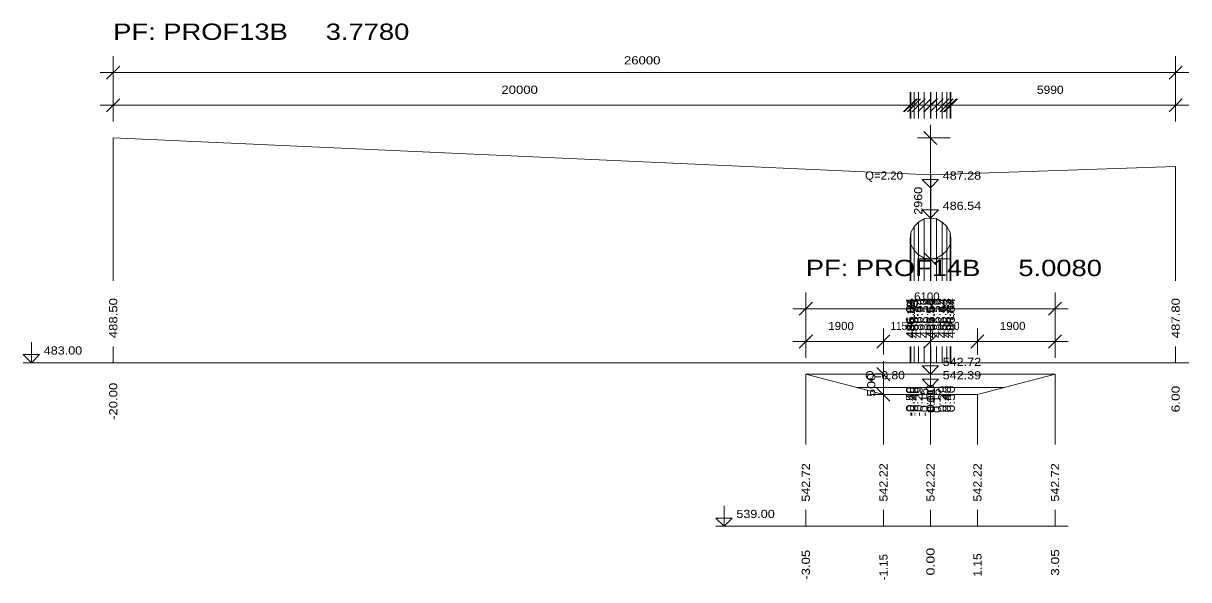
# Model space of a CAD drawing. Extents: x 7 to 442, y -393 to 441.
# Drawn here: x 399.84 to 428.36, y -294.34 to -280.73 of the extents above; entities that cross this region are included whole.
import ezdxf

# ---------------------------------------------------------------- set-up
doc = ezdxf.new("R2010")
doc.units = 0
doc.header["$LTSCALE"] = 0.08
doc.layers.add('7', color=7, linetype='Continuous', lineweight=13)

msp = doc.modelspace()

# ---------------------------------------------------------------- linework, layer by layer
at = {"layer": '7'}
for p, q in [((401.878, -282.094), (402.198, -281.774)), ((402.038, -283.134), (402.038, -281.534)), ((427.878, -282.094), (428.198, -281.774)), ((428.038, -283.134), (428.038, -281.534)), ((401.718, -281.934), (428.358, -281.934)), ((401.878, -282.894), (402.198, -282.574)), ((402.038, -283.054), (402.038, -282.414)), ((421.378, -282.894), (421.698, -282.574)), ((421.398, -282.894), (421.718, -282.574)), ((421.398, -282.894), (421.718, -282.574)), ((421.478, -282.894), (421.798, -282.574)), ((421.478, -282.894), (421.798, -282.574)), ((421.538, -283.054), (421.538, -282.414)), ((421.558, -283.054), (421.558, -282.414)), ((421.558, -283.054), (421.558, -282.414)), ((421.588, -282.894), (421.908, -282.574)), ((421.588, -282.894), (421.908, -282.574)), ((421.638, -283.054), (421.638, -282.414)), ((421.638, -283.054), (421.638, -282.414)), ((421.728, -282.894), (422.048, -282.574)), ((421.728, -282.894), (422.048, -282.574)), ((421.748, -283.054), (421.748, -282.414)), ((421.748, -283.054), (421.748, -282.414)), ((421.878, -282.894), (422.198, -282.574)), ((421.878, -282.894), (422.198, -282.574)), ((421.878, -282.894), (422.198, -282.574)), ((421.888, -283.054), (421.888, -282.414)), ((421.888, -283.054), (421.888, -282.414)), ((421.888, -282.894), (422.208, -282.574)), ((421.888, -282.894), (422.208, -282.574)), ((422.028, -282.894), (422.348, -282.574)), ((422.028, -282.894), (422.348, -282.574)), ((422.038, -283.054), (422.038, -282.414)), ((422.038, -283.054), (422.038, -282.414)), ((422.038, -283.054), (422.038, -282.414)), ((422.048, -283.054), (422.048, -282.414)), ((422.048, -283.054), (422.048, -282.414)), ((422.168, -282.894), (422.488, -282.574)), ((422.168, -282.894), (422.488, -282.574)), ((422.188, -283.054), (422.188, -282.414)), ((422.188, -283.054), (422.188, -282.414)), ((422.278, -282.894), (422.598, -282.574)), ((422.278, -282.894), (422.598, -282.574)), ((422.328, -283.054), (422.328, -282.414)), ((422.328, -283.054), (422.328, -282.414)), ((422.358, -282.894), (422.678, -282.574)), ((422.358, -282.894), (422.678, -282.574)), ((422.378, -282.894), (422.698, -282.574)), ((422.438, -283.054), (422.438, -282.414)), ((422.438, -283.054), (422.438, -282.414)), ((422.518, -283.054), (422.518, -282.414)), ((422.518, -283.054), (422.518, -282.414)), ((422.538, -283.054), (422.538, -282.414)), ((427.878, -282.894), (428.198, -282.574)), ((428.038, -283.054), (428.038, -282.414)), ((401.718, -282.734), (428.358, -282.734)), ((422.198, -283.694), (421.878, -283.374)), ((422.038, -286.654), (422.038, -283.214)), ((402.038, -287.034), (402.038, -283.534)), ((421.718, -283.534), (422.518, -283.534)), ((428.038, -287.034), (428.038, -284.234)), ((422.038, -287.034), (422.038, -284.434)), ((422.048, -287.034), (422.048, -284.434)), ((422.038, -284.754), (422.048, -284.754)), ((421.638, -287.034), (421.638, -285.704)), ((421.748, -287.034), (421.748, -285.594)), ((421.888, -287.034), (421.888, -285.514)), ((422.038, -287.034), (422.038, -285.494)), ((422.038, -285.494), (422.048, -285.494)), ((422.048, -287.034), (422.048, -285.494)), ((422.188, -287.034), (422.188, -285.514)), ((422.328, -287.034), (422.328, -285.594)), ((422.438, -287.034), (422.438, -285.704)), ((421.538, -287.034), (421.538, -285.994)), ((421.558, -287.034), (421.558, -285.844)), ((422.518, -287.034), (422.518, -285.844)), ((422.538, -287.034), (422.538, -285.994)), ((421.558, -287.034), (421.558, -286.144)), ((421.638, -287.034), (421.638, -286.284)), ((422.198, -286.654), (421.878, -286.334)), ((422.438, -287.034), (422.438, -286.284)), ((422.518, -287.034), (422.518, -286.144)), ((421.718, -286.494), (422.518, -286.494)), ((421.748, -287.034), (421.748, -286.394)), ((421.888, -287.034), (421.888, -286.474)), ((422.038, -287.034), (422.038, -286.494)), ((422.188, -287.034), (422.188, -286.474)), ((422.328, -287.034), (422.328, -286.394)), ((418.988, -288.914), (418.988, -287.314)), ((425.088, -288.914), (425.088, -287.314)), ((418.668, -287.714), (425.408, -287.714)), ((418.828, -287.874), (419.148, -287.554)), ((424.928, -287.874), (425.248, -287.554)), ((418.988, -288.834), (418.988, -288.194)), ((420.888, -288.834), (420.888, -288.194)), ((422.038, -288.834), (422.038, -288.194)), ((423.188, -288.834), (423.188, -288.194)), ((425.088, -288.834), (425.088, -288.194)), ((418.668, -288.514), (425.408, -288.514)), ((418.828, -288.674), (419.148, -288.354)), ((420.728, -288.674), (421.048, -288.354)), ((421.878, -288.674), (422.198, -288.354)), ((423.028, -288.674), (423.348, -288.354)), ((424.928, -288.674), (425.248, -288.354)), ((402.038, -289.034), (402.038, -288.634)), ((421.538, -289.034), (421.538, -288.634)), ((421.558, -289.034), (421.558, -288.634)), ((421.558, -289.034), (421.558, -288.634)), ((421.638, -289.034), (421.638, -288.634)), ((421.638, -289.034), (421.638, -288.634)), ((421.748, -289.034), (421.748, -288.634)), ((421.748, -289.034), (421.748, -288.634)), ((421.888, -289.034), (421.888, -288.634)), ((421.888, -289.034), (421.888, -288.634)), ((422.038, -289.034), (422.038, -288.634)), ((422.038, -289.034), (422.038, -288.634)), ((422.038, -289.034), (422.038, -288.634)), ((422.048, -289.034), (422.048, -288.634)), ((422.048, -289.034), (422.048, -288.634)), ((422.188, -289.034), (422.188, -288.634)), ((422.188, -289.034), (422.188, -288.634)), ((422.328, -289.034), (422.328, -288.634)), ((422.328, -289.034), (422.328, -288.634)), ((422.438, -289.034), (422.438, -288.634)), ((422.438, -289.034), (422.438, -288.634)), ((422.518, -289.034), (422.518, -288.634)), ((422.518, -289.034), (422.518, -288.634)), ((422.538, -289.034), (422.538, -288.634)), ((428.038, -289.034), (428.038, -288.634)), ((399.838, -289.034), (428.358, -289.034)), ((421.048, -289.474), (420.728, -289.154)), ((420.888, -289.974), (420.888, -288.994)), ((418.988, -291.034), (418.988, -289.314)), ((418.988, -289.314), (425.088, -289.314)), ((420.568, -289.314), (421.368, -289.314)), ((425.088, -291.034), (425.088, -289.314)), ((420.227, -289.64), (423.849, -289.64)), ((421.048, -289.974), (420.728, -289.654)), ((420.568, -289.814), (421.368, -289.814)), ((420.888, -291.034), (420.888, -289.814)), ((422.038, -291.034), (422.038, -289.814)), ((423.188, -291.034), (423.188, -289.814)), ((418.988, -293.034), (418.988, -292.634)), ((420.888, -293.034), (420.888, -292.634)), ((422.038, -293.034), (422.038, -292.634)), ((423.188, -293.034), (423.188, -292.634)), ((425.088, -293.034), (425.088, -292.634)), ((416.788, -293.034), (425.408, -293.034))]:
    msp.add_line(p, q, dxfattribs=at)
for points in [[(402.038, -283.534), (422.038, -284.434), (422.038, -285.494), (421.888, -285.514), (421.748, -285.594), (421.638, -285.704), (421.558, -285.844), (421.538, -285.994), (421.558, -286.144), (421.638, -286.284), (421.748, -286.394), (421.888, -286.474), (422.038, -286.494), (422.188, -286.474), (422.328, -286.394), (422.438, -286.284), (422.518, -286.144), (422.538, -285.994), (422.518, -285.844), (422.438, -285.704), (422.328, -285.594), (422.188, -285.514), (422.048, -285.494), (422.048, -284.434), (428.038, -284.234)], [(422.038, -284.254), (422.038, -284.754), (421.838, -284.554), (422.238, -284.554), (422.038, -284.754)], [(422.038, -284.994), (422.038, -285.494), (421.838, -285.294), (422.238, -285.294), (422.038, -285.494)], [(400.038, -288.534), (400.038, -289.034), (399.838, -288.834), (400.238, -288.834), (400.038, -289.034)], [(422.038, -288.814), (422.038, -289.314), (421.838, -289.114), (422.238, -289.114), (422.038, -289.314)], [(422.038, -289.14), (422.038, -289.64), (421.838, -289.44), (422.238, -289.44), (422.038, -289.64)], [(418.988, -289.314), (420.888, -289.814), (422.038, -289.814), (423.188, -289.814), (425.088, -289.314)], [(416.988, -292.534), (416.988, -293.034), (416.788, -292.834), (417.188, -292.834), (416.988, -293.034)]]:
    msp.add_lwpolyline(points, dxfattribs=at)

# ---------------------------------------------------------------- texts
for s, height, width, p in [('PF: PROF13B     3.7780', 0.4, 1.25, (402.038, -281.134)), ('26000', 0.2, 1.2, (414.538, -281.734)), ('20000', 0.2, 1.2, (411.538, -282.454)), ('5990', 0.2, 1.1, (424.643, -282.454)), ('Q=2.20', 0.2, 1.05, (420.438, -284.554)), ('487.28', 0.2, 1.15, (422.338, -284.554)), ('486.54', 0.2, 1.15, (422.338, -285.294)), ('PF: PROF14B     5.0080', 0.4, 1.25, (418.988, -286.914)), ('6100', 0.2, 1.05, (421.638, -287.514)), ('1900', 0.2, 1.05, (419.538, -288.234)), ('1150', 0.2, 0.9, (421.063, -288.234)), ('1150', 0.2, 0.9, (422.213, -288.234)), ('1900', 0.2, 1.05, (423.738, -288.234)), ('483.00', 0.2, 1.15, (400.338, -288.834)), ('542.72', 0.2, 1.15, (422.338, -289.114)), ('Q=0.80', 0.2, 1.1, (420.438, -289.44)), ('542.39', 0.2, 1.15, (422.338, -289.44)), ('539.00', 0.2, 1.15, (417.288, -292.834))]:
    msp.add_text(s, height=height, dxfattribs=dict(at, width=width)).set_placement(p)
for s, width, p in [('2960', 1.15, (421.838, -285.414)), ('488.50 ', 1.2, (402.138, -288.434)), ('486.04 ', 1.2, (421.638, -288.434)), ('486.33 ', 1.2, (421.738, -288.434)), ('486.44 ', 1.2, (421.848, -288.434)), ('485.64 ', 1.2, (421.848, -288.434)), ('485.56 ', 1.2, (421.988, -288.434)), ('486.52 ', 1.2, (421.988, -288.434)), ('486.54 ', 1.2, (422.138, -288.434)), ('487.60 ', 1.2, (422.138, -288.434)), ('486.54 ', 1.2, (422.148, -288.434)), ('487.60 ', 1.2, (422.148, -288.434)), ('485.56 ', 1.2, (422.288, -288.434)), ('486.52 ', 1.2, (422.288, -288.434)), ('485.64 ', 1.2, (422.428, -288.434)), ('486.44 ', 1.2, (422.428, -288.434)), ('486.33 ', 1.2, (422.538, -288.434)), ('486.04 ', 1.2, (422.638, -288.434)), ('487.80 ', 1.2, (428.138, -288.434)), ('485.89 ', 1.15, (421.658, -288.434)), ('486.19 ', 1.1, (421.658, -288.434)), ('485.75 ', 1.15, (421.738, -288.434)), ('485.54 ', 1.15, (422.138, -288.434)), ('485.75 ', 1.15, (422.538, -288.434)), ('485.89 ', 1.15, (422.618, -288.434)), ('486.19 ', 1.1, (422.618, -288.434)), (' 500', 1.3, (420.688, -289.964)), ('-20.00 ', 1.2, (402.138, -290.434)), (' -0.50 ', 1.2, (421.638, -290.434)), (' -0.48 ', 1.2, (421.658, -290.434)), (' -0.48 ', 1.2, (421.658, -290.434)), (' -0.40 ', 1.2, (421.738, -290.434)), (' -0.40 ', 1.2, (421.738, -290.434)), (' -0.29 ', 1.2, (421.848, -290.434)), (' -0.29 ', 1.2, (421.848, -290.434)), (' -0.15 ', 1.15, (421.988, -290.434)), (' -0.15 ', 1.15, (421.988, -290.434)), ('  0.00 ', 1.3, (422.138, -290.434)), ('  0.00 ', 1.3, (422.138, -290.434)), ('  0.00 ', 1.3, (422.138, -290.434)), ('  0.01 ', 1.15, (422.148, -290.434)), ('  0.01 ', 1.15, (422.148, -290.434)), ('  0.15 ', 1.15, (422.288, -290.434)), ('  0.15 ', 1.15, (422.288, -290.434)), ('  0.29 ', 1.25, (422.428, -290.434)), ('  0.29 ', 1.25, (422.428, -290.434)), ('  0.40 ', 1.25, (422.538, -290.434)), ('  0.40 ', 1.25, (422.538, -290.434)), ('  0.48 ', 1.25, (422.618, -290.434)), ('  0.48 ', 1.25, (422.618, -290.434)), ('  0.50 ', 1.25, (422.638, -290.434)), ('  6.00 ', 1.25, (428.138, -290.434)), ('542.72 ', 1.15, (419.088, -292.434)), ('542.22 ', 1.15, (420.988, -292.434)), ('542.22 ', 1.15, (422.138, -292.434)), ('542.22 ', 1.15, (423.288, -292.434)), ('542.72 ', 1.15, (425.188, -292.434)), (' -3.05 ', 1.2, (419.088, -294.434)), (' -1.15 ', 1.05, (420.988, -294.434)), ('  0.00 ', 1.3, (422.138, -294.434)), ('  1.15 ', 1.1, (423.288, -294.434)), ('  3.05 ', 1.25, (425.188, -294.434))]:
    msp.add_text(s, height=0.2, rotation=90, dxfattribs=dict(at, width=width)).set_placement(p)

doc.saveas('drawing.dxf')
